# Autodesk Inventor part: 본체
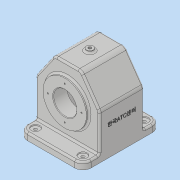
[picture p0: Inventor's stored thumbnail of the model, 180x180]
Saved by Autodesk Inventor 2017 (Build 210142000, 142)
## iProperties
Part Number: 본체
Material: 일반
Document SubType Name: Modeling
Designer: MRC
Density: 1 g/cm^3
Appearance: 기본값
Author: MRC
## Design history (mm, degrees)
sketch "스케치1"
  geometry: L1 (-23.491, 57)-(-55, 12); L2 (-55, 12)-(-55, -65); L3 (-55, -65)-(55, -65); L4 (55, -65)-(55, 12); L5 (55, 12)-(23.491, 57); L6 (23.491, 57)-(-23.491, 57); 2 further points
  constraints: 12 end point, 3 perpendicular, 1 midpoint, 1 vertical, 1 vertical alignment
  dimensions: "d0" = 77 distance of L1.end L2.end; "d1" = 35 deg angle of L2 L1; "d2" = 35 deg angle of L5 L4; "d3" = 122 distance between parallel lines of L6 L3; "d4" = 77 distance of L3.end L4.end; "d5" = 110 distance of L2.end L3.end; "d6" = 65 distance from line of point (0, 0) L3
extrude "돌출1" new body sketch "스케치1" stored distance "d7" = 77; taper "d8" = 0 deg
feature "쉘1" dims "d9" = 5
sketch "스케치2"
  geometry: L1 (0, 0)-(110, 0) reference; L2 (110, 0)-(110, 28.5); L3 (110, 28.5)-(0, 28.5); L4 (0, 28.5)-(0, 0); L5 (31.509, 0)-(0, 0) reference; L6 (0, -77)-(0, 0) reference; 1 further point
  constraints: 6 end point, 2 perpendicular, 1 collinear, 1 point on line, 1 vertical
  dimensions: "d10" = 67 distance from line of L3 point (55, -38.5)
extrude "돌출2" join sketch "스케치2" distance "d11" = 12; taper "d12" = 0 deg
sketch "스케치3"
  geometry: C1 r 6 at (23.491, 38.5); 1 further point
  constraints: 1 centre point, 1 coincident
  dimensions: "d13" = 6 radius of C1
extrude "돌출3" join sketch "스케치3" distance "d14" = 4; taper "d15" = 0 deg
sketch "스케치4"
  geometry: C1 r 37.5 at (0, 0); 1 further point
  constraints: 1 centre point, 1 coincident
  dimensions: "d16" = 75 diameter of C1
extrude "돌출4" join sketch "스케치4" distance "d17" = 5; taper "d18" = 0 deg
sketch "스케치5"
  geometry: C1 r 31 at (0, 0); 1 further point
  constraints: 1 centre point, 1 coincident
  dimensions: "d19" = 62 diameter of C1
extrude "돌출5" join sketch "스케치5" distance "d20" = 10; taper "d21" = 0 deg
node "작업 평면1"
sketch "스케치6"
  geometry: C1 r 27 at (0, 0); 1 further point
  constraints: 1 centre point, 1 coincident
  dimensions: "d23" = 54 diameter of C1
extrude "돌출6" join sketch "스케치6" stored distance "d24" = 10; taper "d25" = 45 deg
hole "구멍1" diameter "d28" = 40; stored, may be unused: countersink angle "d32" = 90 deg, drill point angle "d34" = 118 deg; dims "d26" = 10, "d27" = 10, "d29" = 6, "d30" = 4, "d31" = 2, "d33" = 24
hole "구멍2" diameter "d37" = 40; stored, may be unused: countersink angle "d41" = 90 deg, drill point angle "d43" = 118 deg; dims "d35" = 10, "d36" = 10, "d38" = 6, "d39" = 4, "d40" = 2, "d42" = 15
fillet "모깎기1" dims "d44" = 14
sketch "스케치7"
  geometry: A1 r 14 centre (14, 91.5) between (14, 105.5) and (0, 91.5) reference; A2 r 14 centre (96, 91.5) between (110, 91.5) and (96, 105.5) reference; A3 r 14 centre (96, -14.5) between (96, -28.5) and (110, -14.5) reference; A4 r 14 centre (14, -14.5) between (0, -14.5) and (14, -28.5) reference; 5 further points
  constraints: 4 coincident
hole "구멍3" sketch "스케치7" at (14, 91.5), (96, 91.5), (96, -14.5), (14, -14.5) diameter "d45" = 5.5; stored, may be unused: countersink angle "d49" = 90 deg, drill point angle "d51" = 118 deg; dims "d46" = 6, "d47" = 15, "d48" = 2, "d50" = 15
hole "구멍4" diameter "d54" = 5.188; stored, may be unused: countersink angle "d58" = 90 deg, drill point angle "d60" = 118 deg; dims "d52" = 10, "d53" = 10, "d55" = 20, "d56" = 15, "d57" = 2, "d59" = 20
sketch "스케치8"
  geometry: A1 r 29 centre (0, 0) between (0, 29) and (-29, 0); 3 further points
  constraints: 4 point on circle, 1 centre point, 1 coincident
  dimensions: "d61" = 58 diameter of A1
hole "구멍5" sketch "스케치8" at (0, 29), (-29, 0), (0, -29), (29, 0) diameter "d62" = 2.459; stored, may be unused: countersink angle "d66" = 90 deg, drill point angle "d68" = 118 deg; dims "d63" = 6, "d64" = 15, "d65" = 2, "d67" = 8
sketch "스케치9"
  geometry: A1 r 26 centre (0, 0) between (0, 26) and (-26, 0); 3 further points
  constraints: 4 point on circle, 1 centre point, 1 coincident
  dimensions: "d69" = 52 diameter of A1
hole "구멍6" sketch "스케치9" at (0, 26), (-26, 0), (0, -26), (26, 0) diameter "d70" = 2.459; stored, may be unused: countersink angle "d74" = 90 deg, drill point angle "d76" = 118 deg; dims "d71" = 6, "d72" = 15, "d73" = 2, "d75" = 8
node "작업 평면2"
sketch "스케치10"
  geometry: L1 (-53, 67)-(-65, 67) reference; L2 (-65, -53)-(-65, 53) reference; L3 (-53, 38.5)-(12, 38.5) reference; 2 further points
  constraints: 1 other
  dimensions: "d79" = 50 distance from line of L2 point (-15, 0); "d87" = 28.5 distance between parallel lines of L3 L1 (derived); "d88" = 38.5 distance from line of point (-15, 0) L3
feature "엠보싱1" sketch "스케치10" dims "d80" = 0.5, "d81" = 0
fillet "모깎기2" dims "d82" = 10
chamfer "모따기1" distance "d84" = 1; stored, may be unused: second distance "d85" = 2, angle "d86" = 45 deg
fillet "모깎기4" dims "d89" = 5
fillet "모깎기5" dims "d90" = 3
node "솔리드1"
mirror "미러1"
other parameters: "d22" = -24, "d77" = 63.25
